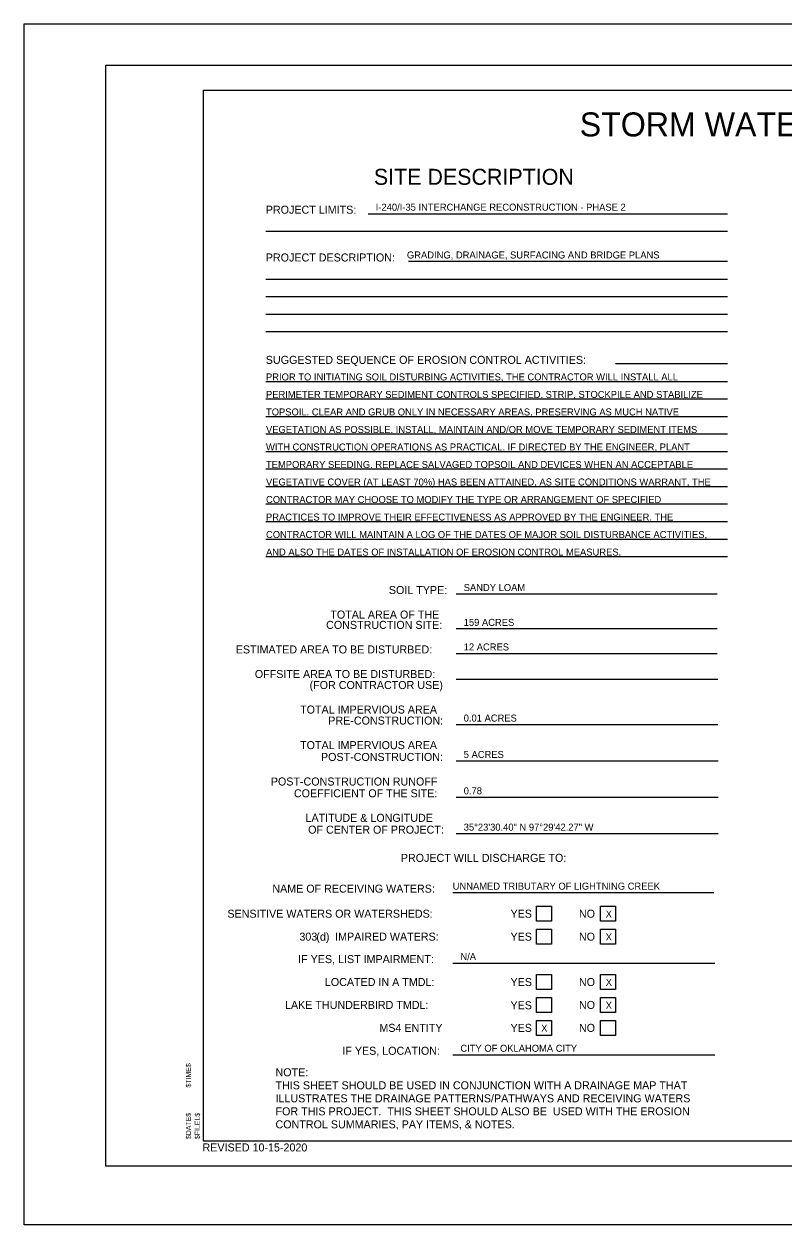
# Model space of a CAD drawing. Extents: x 1975980 to 1976688, y 470504 to 470744.
# Drawn here: x 1976328 to 1976479.8, y 470504.2 to 470744.2 of the extents above; entities that cross this region are included whole.
import ezdxf

# ---------------------------------------------------------------- set-up
doc = ezdxf.new("R2010")
doc.units = 0
for name, color, linetype in [('SHT_Plot_Shape_Full', 7, 'Continuous'), ('SHT_Plot_Shape_Half', 7, 'Continuous'), ('SHT_Plot_Stamp', 7, 'Continuous'), ('SHT_Sheet_Border', 7, 'Continuous')]:
    doc.layers.add(name, color=color, linetype=linetype)

msp = doc.modelspace()

# ---------------------------------------------------------------- linework, layer by layer
for p, q in [((1976396.71, 470706.29), (1976468.5, 470706.29)), ((1976376.27, 470702.79), (1976468.5, 470702.79)), ((1976468.5, 470696.74), (1976404.74, 470696.74)), ((1976376.27, 470693.24), (1976468.5, 470693.24)), ((1976376.27, 470689.74), (1976468.5, 470689.74)), ((1976376.27, 470686.24), (1976468.5, 470686.24)), ((1976376.27, 470682.74), (1976468.5, 470682.74)), ((1976468.5, 470676.28), (1976446.14, 470676.28)), ((1976376.27, 470672.78), (1976468.5, 470672.78)), ((1976376.27, 470669.28), (1976468.5, 470669.28)), ((1976376.27, 470665.78), (1976468.5, 470665.78)), ((1976376.27, 470662.28), (1976468.5, 470662.28)), ((1976376.27, 470658.78), (1976468.5, 470658.78)), ((1976376.27, 470655.28), (1976468.5, 470655.28)), ((1976376.27, 470651.78), (1976468.5, 470651.78)), ((1976376.27, 470648.28), (1976468.5, 470648.28)), ((1976376.27, 470644.78), (1976468.5, 470644.78)), ((1976376.27, 470641.28), (1976468.5, 470641.28)), ((1976376.27, 470637.78), (1976468.5, 470637.78)), ((1976466.45, 470630.28), (1976414.29, 470630.28)), ((1976466.45, 470623.32), (1976414.29, 470623.32)), ((1976414.29, 470618.41), (1976466.45, 470618.41)), ((1976414.29, 470613.3), (1976466.54, 470613.3)), ((1976414.29, 470604.2), (1976466.54, 470604.2)), ((1976414.29, 470596.93), (1976466.62, 470596.93)), ((1976414.29, 470589.66), (1976466.62, 470589.66)), ((1976414.29, 470582.4), (1976466.62, 470582.4)), ((1976413.62, 470570.61), (1976465.78, 470570.61)), ((1976413.62, 470556.53), (1976465.96, 470556.53)), ((1976413.62, 470538.21), (1976465.96, 470538.21))]:
    msp.add_line(p, q)
for points in [[(1976430.32, 470567.9), (1976433.32, 470567.9), (1976433.32, 470564.9), (1976430.32, 470564.9)], [(1976443.13, 470567.9), (1976446.13, 470567.9), (1976446.13, 470564.9), (1976443.13, 470564.9)], [(1976430.32, 470563.32), (1976433.32, 470563.32), (1976433.32, 470560.32), (1976430.32, 470560.32)], [(1976443.13, 470563.32), (1976446.13, 470563.32), (1976446.13, 470560.32), (1976443.13, 470560.32)], [(1976430.32, 470554.25), (1976433.32, 470554.25), (1976433.32, 470551.25), (1976430.32, 470551.25)], [(1976443.13, 470554.25), (1976446.13, 470554.25), (1976446.13, 470551.25), (1976443.13, 470551.25)], [(1976430.32, 470549.67), (1976433.32, 470549.67), (1976433.32, 470546.67), (1976430.32, 470546.67)], [(1976443.13, 470549.67), (1976446.13, 470549.67), (1976446.13, 470546.67), (1976443.13, 470546.67)], [(1976430.32, 470545.09), (1976433.32, 470545.09), (1976433.32, 470542.09), (1976430.32, 470542.09)], [(1976443.13, 470545.09), (1976446.13, 470545.09), (1976446.13, 470542.09), (1976443.13, 470542.09)]]:
    msp.add_lwpolyline(points, close=True)
at = {"layer": 'SHT_Plot_Shape_Full'}
msp.add_lwpolyline([(1976327.98, 470744.2), (1976687.98, 470744.2), (1976687.98, 470504.2), (1976327.98, 470504.2)], close=True, dxfattribs=at)
at = {"layer": 'SHT_Plot_Shape_Half'}
msp.add_lwpolyline([(1976344.35, 470735.95), (1976684.35, 470735.95), (1976684.35, 470515.95), (1976344.35, 470515.95)], close=True, dxfattribs=at)
at = {"layer": 'SHT_Sheet_Border'}
msp.add_lwpolyline([(1976678.85, 470520.95), (1976363.85, 470520.95), (1976363.85, 470730.95), (1976678.85, 470730.95)], close=True, dxfattribs=at)

# ---------------------------------------------------------------- texts
for s, height, p in [('STORM WATER MANAGEMENT PLAN', 4.8011, (1976438.97, 470721.73)), ('SITE DESCRIPTION', 3.2007, (1976397.85, 470712.06)), ('PROJECT LIMITS:', 1.6, (1976376.27, 470706.29)), ('I-240/I-35 INTERCHANGE RECONSTRUCTION - PHASE 2', 1.4, (1976398.23, 470706.89)), ('PROJECT DESCRIPTION:', 1.6, (1976376.27, 470696.74)), ('GRADING, DRAINAGE, SURFACING AND BRIDGE PLANS', 1.4, (1976404.46, 470697.34)), ('SUGGESTED SEQUENCE OF EROSION CONTROL ACTIVITIES:', 1.6, (1976376.27, 470676.28)), ('PRIOR TO INITIATING SOIL DISTURBING ACTIVITIES, THE CONTRACTOR WILL INSTALL ALL ', 1.4, (1976376.31, 470672.97)), ('PERIMETER TEMPORARY SEDIMENT CONTROLS SPECIFIED. STRIP, STOCKPILE AND STABILIZE ', 1.4, (1976376.31, 470669.47)), ('TOPSOIL. CLEAR AND GRUB ONLY IN NECESSARY AREAS, PRESERVING AS MUCH NATIVE ', 1.4, (1976376.31, 470665.97)), ('VEGETATION AS POSSIBLE. INSTALL, MAINTAIN AND/OR MOVE TEMPORARY SEDIMENT ITEMS ', 1.4, (1976376.31, 470662.47)), ('WITH CONSTRUCTION OPERATIONS AS PRACTICAL. IF DIRECTED BY THE ENGINEER, PLANT ', 1.4, (1976376.31, 470658.97)), ('TEMPORARY SEEDING. REPLACE SALVAGED TOPSOIL AND DEVICES WHEN AN ACCEPTABLE ', 1.4, (1976376.31, 470655.47)), ('VEGETATIVE COVER (AT LEAST 70%) HAS BEEN ATTAINED. AS SITE CONDITIONS WARRANT, THE ', 1.4, (1976376.31, 470651.97)), ('CONTRACTOR MAY CHOOSE TO MODIFY THE TYPE OR ARRANGEMENT OF SPECIFIED ', 1.4, (1976376.31, 470648.47)), ('PRACTICES TO IMPROVE THEIR EFFECTIVENESS AS APPROVED BY THE ENGINEER. THE ', 1.4, (1976376.31, 470644.97)), ('CONTRACTOR WILL MAINTAIN A LOG OF THE DATES OF MAJOR SOIL DISTURBANCE ACTIVITIES, ', 1.4, (1976376.31, 470641.47)), ('AND ALSO THE DATES OF INSTALLATION OF EROSION CONTROL MEASURES.', 1.4, (1976376.31, 470637.97)), ('SOIL TYPE:', 1.6, (1976400.85, 470630.28)), ('SANDY LOAM', 1.4, (1976415.8, 470630.88)), ('TOTAL AREA OF THE', 1.6, (1976389.16, 470625.38)), ('CONSTRUCTION SITE:', 1.6, (1976388.32, 470623.32)), ('159 ACRES', 1.4, (1976415.8, 470623.92)), ('ESTIMATED AREA TO BE DISTURBED:', 1.6, (1976370.27, 470618.41)), ('12 ACRES', 1.4, (1976415.8, 470619.01)), ('OFFSITE AREA TO BE DISTURBED:', 1.6, (1976374.08, 470613.5)), ('(FOR CONTRACTOR USE)', 1.6, (1976385.02, 470611.3)), ('TOTAL IMPERVIOUS AREA ', 1.6, (1976383.12, 470606.4)), ('PRE-CONSTRUCTION:', 1.6, (1976388.75, 470604.2)), ('0.01 ACRES', 1.4, (1976415.8, 470604.8)), ('TOTAL IMPERVIOUS AREA ', 1.6, (1976383.12, 470599.29)), ('POST-CONSTRUCTION:', 1.6, (1976387.29, 470596.93)), ('5 ACRES', 1.4, (1976415.8, 470597.53)), ('POST-CONSTRUCTION RUNOFF', 1.6, (1976377.27, 470592.02)), ('COEFFICIENT OF THE SITE:', 1.6, (1976381.89, 470589.66)), ('0.78', 1.4, (1976415.8, 470590.26)), ('LATITUDE & LONGITUDE', 1.6, (1976384.2, 470584.76)), ('OF CENTER OF PROJECT:', 1.6, (1976384.73, 470582.4)), ('35°23\'30.40" N 97°29\'42.27" W', 1.4, (1976415.8, 470583)), ('PROJECT WILL DISCHARGE TO:', 1.6, (1976403.24, 470576.76)), ('NAME OF RECEIVING WATERS:', 1.6, (1976377.58, 470570.61)), ('UNNAMED TRIBUTARY OF LIGHTNING CREEK', 1.4, (1976413.6, 470571.21)), ('SENSITIVE WATERS OR WATERSHEDS:', 1.6, (1976368.6, 470565.6)), ('YES', 1.6, (1976425.15, 470565.6)), ('NO', 1.6, (1976438.82, 470565.6)), ('X', 1.4, (1976444.16, 470565.63)), ('303      IMPAIRED WATERS:', 1.6, (1976382.98, 470561.02)), ('(d)', 1.6, (1976386.37, 470561.02)), ('YES', 1.6, (1976425.15, 470561.02)), ('NO', 1.6, (1976438.82, 470561.02)), ('X', 1.4, (1976444.16, 470561.05)), ('N/A', 1.4, (1976415.14, 470557.13)), ('IF YES, LIST IMPAIRMENT:', 1.6, (1976382.73, 470556.53)), ('LOCATED IN A TMDL:', 1.6, (1976388.07, 470551.95)), ('YES', 1.6, (1976425.15, 470551.95)), ('NO', 1.6, (1976438.82, 470551.95)), ('X', 1.4, (1976444.16, 470551.98)), ('LAKE THUNDERBIRD TMDL:', 1.6, (1976380.11, 470547.37)), ('YES', 1.6, (1976425.15, 470547.3)), ('NO', 1.6, (1976438.82, 470547.37)), ('X', 1.4, (1976444.16, 470547.4)), ('MS4 ENTITY', 1.6, (1976398.96, 470542.79)), ('YES', 1.6, (1976425.15, 470542.79)), ('X', 1.4, (1976431.27, 470542.82)), ('NO', 1.6, (1976438.82, 470542.79)), ('IF YES, LOCATION:', 1.6, (1976391.56, 470538.21)), ('CITY OF OKLAHOMA CITY', 1.4, (1976415.14, 470538.81)), ('NOTE:', 1.6, (1976378.21, 470533.91)), ('THIS SHEET SHOULD BE USED IN CONJUNCTION WITH A DRAINAGE MAP THAT ', 1.6, (1976378.21, 470531.31)), ('ILLUSTRATES THE DRAINAGE PATTERNS/PATHWAYS AND RECEIVING WATERS', 1.6, (1976378.21, 470528.71)), ('FOR THIS PROJECT.  THIS SHEET SHOULD ALSO BE  USED WITH THE EROSION', 1.6, (1976378.21, 470526.11)), ('CONTROL SUMMARIES, PAY ITEMS, & NOTES. ', 1.6, (1976378.21, 470523.51)), ('REVISED 10-15-2020', 1.6004, (1976363.63, 470518.89))]:
    msp.add_text(s, height=height).set_placement(p)
at = {"layer": 'SHT_Plot_Stamp'}
for s, p in [('$TIME$', (1976361.31, 470531.67)), ('$DATE$', (1976361.31, 470521.37)), ('$FILEL$', (1976363.08, 470521.37))]:
    msp.add_text(s, height=1, rotation=90, dxfattribs=at).set_placement(p)

doc.saveas('drawing.dxf')
